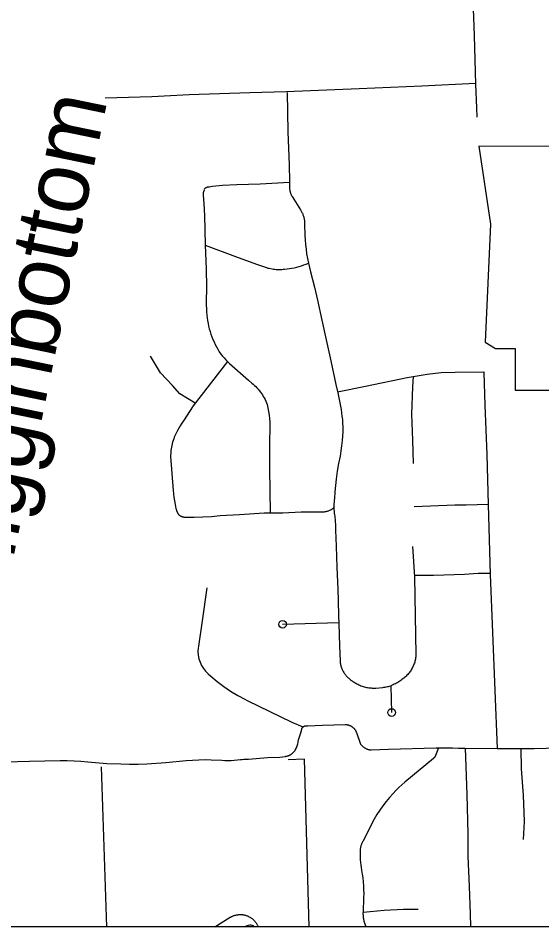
# Model space of a CAD drawing. Extents: x 309348 to 309445, y 336383 to 336484.
# Drawn here: x 309348.942 to 309349.625, y 336395.727 to 336396.912 of the extents above; entities that cross this region are included whole.
import ezdxf

# ---------------------------------------------------------------- set-up
doc = ezdxf.new("R2010")
doc.units = 0
doc.layers.add('R_Annotation', color=7, linetype='Continuous')
doc.layers.add('R_Border Notes', color=7, linetype='Continuous')

msp = doc.modelspace()

# ---------------------------------------------------------------- linework, layer by layer
at = {"layer": 'R_Annotation'}
for points in [[(309349.533, 336396.9923), (309349.5334, 336396.983), (309349.5352, 336396.9367), (309349.537, 336396.8896), (309349.5383, 336396.8422), (309349.5389, 336396.826)], [(309349.5389, 336396.8271), (309349.4687, 336396.8236), (309349.3869, 336396.82), (309349.2917, 336396.8162), (309349.2442, 336396.815), (309349.165, 336396.8123), (309349.1163, 336396.8097), (309349.0557, 336396.8079)], [(309349.5389, 336396.826), (309349.5401, 336396.7954), (309349.5405, 336396.783)], [(309349.2929, 336396.8154), (309349.2941, 336396.7641), (309349.2956, 336396.7209), (309349.2961, 336396.6994), (309349.2961, 336396.6972)], [(309349.1851, 336396.6894), (309349.1852, 336396.6896), (309349.1854, 336396.6898), (309349.1856, 336396.69), (309349.1858, 336396.6902), (309349.186, 336396.6904), (309349.1862, 336396.6906), (309349.1864, 336396.6908), (309349.1866, 336396.6909), (309349.1869, 336396.6911), (309349.1871, 336396.6913), (309349.1873, 336396.6914), (309349.1876, 336396.6915), (309349.1878, 336396.6917), (309349.1881, 336396.6918), (309349.1883, 336396.6919), (309349.1886, 336396.692), (309349.1889, 336396.6921), (309349.1891, 336396.6921), (309349.1894, 336396.6922), (309349.1897, 336396.6923), (309349.1899, 336396.6923), (309349.1902, 336396.6924), (309349.1905, 336396.6924), (309349.1908, 336396.6924), (309349.191, 336396.6924), (309349.1913, 336396.6924), (309349.1956, 336396.6931), (309349.1999, 336396.6936), (309349.2042, 336396.6941), (309349.2085, 336396.6943), (309349.2273, 336396.6954), (309349.2578, 336396.6964), (309349.2961, 336396.6984)], [(309349.2961, 336396.6972), (309349.2962, 336396.6914), (309349.2962, 336396.6906), (309349.2962, 336396.6899), (309349.2963, 336396.6891), (309349.2964, 336396.6883), (309349.2966, 336396.6875), (309349.2967, 336396.6868), (309349.2969, 336396.686), (309349.2971, 336396.6853), (309349.2973, 336396.6845), (309349.2976, 336396.6838), (309349.2979, 336396.683), (309349.2982, 336396.6823), (309349.2985, 336396.6816), (309349.2989, 336396.6809), (309349.2993, 336396.6802), (309349.2997, 336396.6796), (309349.3103, 336396.6624), (309349.3109, 336396.6616), (309349.3114, 336396.6607), (309349.3119, 336396.6597), (309349.3124, 336396.6588), (309349.3129, 336396.6578), (309349.3133, 336396.6569), (309349.3137, 336396.6559), (309349.3141, 336396.6549), (309349.3144, 336396.6539), (309349.3147, 336396.6529), (309349.315, 336396.6518), (309349.3152, 336396.6508), (309349.3154, 336396.6497), (309349.3156, 336396.6487), (309349.3157, 336396.6476), (309349.3157, 336396.6466), (309349.3158, 336396.6455), (309349.3158, 336396.6444), (309349.3158, 336396.6434), (309349.3163, 336396.629), (309349.3166, 336396.623), (309349.317, 336396.6169), (309349.3177, 336396.6108), (309349.3185, 336396.6048), (309349.3195, 336396.5988), (309349.3207, 336396.5928)], [(309349.1851, 336396.6882), (309349.1849, 336396.688), (309349.1847, 336396.6878), (309349.1846, 336396.6876), (309349.1844, 336396.6873), (309349.1843, 336396.6871), (309349.1842, 336396.6868), (309349.1841, 336396.6866), (309349.1839, 336396.6863), (309349.1838, 336396.6861), (309349.1838, 336396.6858), (309349.1837, 336396.6855), (309349.1836, 336396.6853), (309349.1835, 336396.685), (309349.1835, 336396.6847), (309349.1834, 336396.6845), (309349.1834, 336396.6842), (309349.1834, 336396.6839), (309349.1834, 336396.6836), (309349.1834, 336396.6834), (309349.1834, 336396.6831), (309349.1834, 336396.6828), (309349.1834, 336396.6825), (309349.1834, 336396.6823), (309349.1835, 336396.682), (309349.1835, 336396.6817), (309349.1836, 336396.6814), (309349.1843, 336396.67), (309349.1851, 336396.655), (309349.1859, 336396.6171), (309349.186, 336396.6161)], [(309349.186, 336396.6161), (309349.1872, 336396.5854), (309349.1878, 336396.5614), (309349.1874, 336396.542), (309349.1874, 336396.5377), (309349.1876, 336396.5334), (309349.1879, 336396.5291), (309349.1884, 336396.5249), (309349.1888, 336396.5213), (309349.1893, 336396.5177), (309349.1899, 336396.5141), (309349.1906, 336396.5106), (309349.1915, 336396.507), (309349.1925, 336396.5035), (309349.1936, 336396.5001), (309349.1948, 336396.4967), (309349.1961, 336396.4933), (309349.1976, 336396.49), (309349.1992, 336396.4867), (309349.2008, 336396.4835), (309349.2026, 336396.4803), (309349.2045, 336396.4772), (309349.2065, 336396.4742), (309349.2086, 336396.4716), (309349.2108, 336396.4691), (309349.213, 336396.4667), (309349.2153, 336396.4643)], [(309349.186, 336396.6161), (309349.2257, 336396.6013), (309349.253, 336396.5914), (309349.2662, 336396.5869), (309349.268, 336396.5864), (309349.2697, 336396.586), (309349.2715, 336396.5856), (309349.2733, 336396.5852), (309349.2751, 336396.5849), (309349.2769, 336396.5847), (309349.2788, 336396.5846), (309349.2806, 336396.5845), (309349.2824, 336396.5844), (309349.2842, 336396.5845), (309349.2861, 336396.5846), (309349.2879, 336396.5847), (309349.2897, 336396.5849), (309349.2929, 336396.5852), (309349.2961, 336396.5857), (309349.2993, 336396.5862), (309349.3024, 336396.5868), (309349.3055, 336396.5876), (309349.3086, 336396.5884), (309349.3117, 336396.5894), (309349.3148, 336396.5904), (309349.3178, 336396.5916), (309349.3207, 336396.5928)], [(309349.3207, 336396.5928), (309349.3221, 336396.5871), (309349.3236, 336396.5814), (309349.3286, 336396.5612), (309349.3326, 336396.5444), (309349.3383, 336396.5182), (309349.344, 336396.4928), (309349.3501, 336396.4651), (309349.3566, 336396.4346), (309349.359, 336396.4234)], [(309349.1732, 336396.4101), (309349.1531, 336396.4223), (309349.1434, 336396.4329), (309349.1276, 336396.4496), (309349.1146, 336396.4715)], [(309349.2153, 336396.4643), (309349.1706, 336396.4067)], [(309349.2153, 336396.4643), (309349.2179, 336396.4617), (309349.2425, 336396.4401), (309349.2471, 336396.4363), (309349.2488, 336396.4348), (309349.2505, 336396.4332), (309349.2521, 336396.4316), (309349.2537, 336396.4299), (309349.2552, 336396.4282), (309349.2567, 336396.4264), (309349.2581, 336396.4246), (309349.2595, 336396.4227), (309349.2607, 336396.4208), (309349.2619, 336396.4189), (309349.2631, 336396.4169), (309349.2642, 336396.4148), (309349.2652, 336396.4128), (309349.2661, 336396.4107), (309349.2669, 336396.4085), (309349.2679, 336396.4039)], [(309349.3586, 336396.425), (309349.3951, 336396.4324), (309349.4496, 336396.4436), (309349.4573, 336396.4448), (309349.4756, 336396.4481), (309349.4939, 336396.45), (309349.5122, 336396.4505), (309349.5497, 336396.451)], [(309349.4573, 336396.4448), (309349.4564, 336396.4312), (309349.4554, 336396.3957), (309349.4567, 336396.3617), (309349.4573, 336396.3315)], [(309349.5497, 336396.451), (309349.5497, 336396.4501)], [(309349.5497, 336396.4501), (309349.5512, 336396.4073)], [(309349.359, 336396.4234), (309349.3626, 336396.406), (309349.3634, 336396.4017), (309349.3641, 336396.3974), (309349.3646, 336396.3931), (309349.3651, 336396.3887), (309349.3653, 336396.3844), (309349.3655, 336396.3786), (309349.3655, 336396.3728), (309349.3653, 336396.3671), (309349.3649, 336396.3613), (309349.3641, 336396.3546), (309349.3632, 336396.3478), (309349.3621, 336396.3411), (309349.3602, 336396.3315), (309349.3585, 336396.3213), (309349.357, 336396.311), (309349.356, 336396.3026), (309349.3553, 336396.2942), (309349.3548, 336396.2858), (309349.3545, 336396.2834), (309349.3542, 336396.281), (309349.3541, 336396.2786), (309349.354, 336396.2762), (309349.354, 336396.2738)], [(309349.1706, 336396.4067), (309349.1576, 336396.3869), (309349.1555, 336396.3838), (309349.1536, 336396.3807), (309349.1517, 336396.3775), (309349.1499, 336396.3742), (309349.1482, 336396.3709), (309349.1466, 336396.3676), (309349.1458, 336396.3655), (309349.145, 336396.3635), (309349.1442, 336396.3614), (309349.1436, 336396.3593), (309349.143, 336396.3571), (309349.1425, 336396.355), (309349.142, 336396.3528), (309349.1416, 336396.3507), (309349.1413, 336396.3485), (309349.1411, 336396.3463), (309349.141, 336396.3407), (309349.1445, 336396.2962), (309349.1454, 336396.2875), (309349.147, 336396.2779), (309349.148, 336396.2727), (309349.1482, 336396.2718), (309349.1493, 336396.2686), (309349.1509, 336396.2655), (309349.1514, 336396.2647)], [(309349.5512, 336396.4073), (309349.5534, 336396.3433)], [(309349.2679, 336396.4039), (309349.2688, 336396.3993), (309349.2694, 336396.3946), (309349.27, 336396.3899), (309349.2703, 336396.3852), (309349.2705, 336396.3805), (309349.2706, 336396.3758), (309349.2705, 336396.3711), (309349.2702, 336396.3664), (309349.2702, 336396.3247), (309349.2709, 336396.267)], [(309349.5534, 336396.3433), (309349.5555, 336396.2778)], [(309349.5555, 336396.2778), (309349.5268, 336396.277), (309349.5117, 336396.277), (309349.4589, 336396.2748)], [(309349.5555, 336396.2778), (309349.558, 336396.1867)], [(309349.1514, 336396.2647), (309349.1517, 336396.2644), (309349.1521, 336396.2641), (309349.1524, 336396.2639), (309349.1528, 336396.2636), (309349.1531, 336396.2634), (309349.1535, 336396.2632), (309349.1539, 336396.263), (309349.1543, 336396.2628), (309349.1546, 336396.2626), (309349.155, 336396.2624), (309349.1554, 336396.2622), (309349.1558, 336396.2621), (309349.1563, 336396.262), (309349.1567, 336396.2618), (309349.1571, 336396.2617), (309349.1575, 336396.2616), (309349.1579, 336396.2616), (309349.1584, 336396.2615), (309349.1588, 336396.2615), (309349.1592, 336396.2614), (309349.1596, 336396.2614), (309349.1601, 336396.2614), (309349.1605, 336396.2614), (309349.1719, 336396.2614), (309349.1832, 336396.2617), (309349.1945, 336396.2624), (309349.2058, 336396.2635)], [(309349.2058, 336396.2635), (309349.2309, 336396.265), (309349.263, 336396.267), (309349.2709, 336396.267)], [(309349.2709, 336396.267), (309349.2873, 336396.2671), (309349.3114, 336396.2681), (309349.3378, 336396.2683), (309349.3386, 336396.2683), (309349.3394, 336396.2683), (309349.3402, 336396.2683), (309349.341, 336396.2684), (309349.3418, 336396.2685), (309349.3426, 336396.2686), (309349.3434, 336396.2687), (309349.3441, 336396.2689), (309349.3449, 336396.2691), (309349.3457, 336396.2693), (309349.3464, 336396.2695), (309349.3472, 336396.2698), (309349.3479, 336396.2701), (309349.3487, 336396.2704), (309349.3494, 336396.2708), (309349.3501, 336396.2711), (309349.3508, 336396.2715), (309349.3515, 336396.2719), (309349.3521, 336396.2724), (309349.3528, 336396.2728), (309349.3534, 336396.2733), (309349.354, 336396.2738)], [(309349.354, 336396.2738), (309349.3541, 336396.2715), (309349.3542, 336396.2691), (309349.3545, 336396.2667), (309349.3548, 336396.2644), (309349.3551, 336396.2627), (309349.3556, 336396.2566), (309349.3561, 336396.2505), (309349.3563, 336396.2444), (309349.3569, 336396.2237), (309349.3579, 336396.1956), (309349.359, 336396.1676), (309349.3596, 336396.152), (309349.36, 336396.1325), (309349.3603, 336396.1227)], [(309349.4565, 336396.223), (309349.459, 336396.1837)], [(309349.459, 336396.1837), (309349.4611, 336396.082), (309349.461, 336396.0806), (309349.4609, 336396.0791), (309349.4607, 336396.0777), (309349.4605, 336396.0763), (309349.4602, 336396.0749), (309349.4598, 336396.0735), (309349.4595, 336396.0722), (309349.459, 336396.0708), (309349.4585, 336396.0694), (309349.458, 336396.0681), (309349.4574, 336396.0668), (309349.4568, 336396.0655), (309349.4562, 336396.0642), (309349.4555, 336396.063), (309349.4547, 336396.0618), (309349.4539, 336396.0606), (309349.4531, 336396.0594), (309349.4522, 336396.0583), (309349.4513, 336396.0572), (309349.4504, 336396.0561), (309349.4494, 336396.0551), (309349.4484, 336396.0541), (309349.4473, 336396.0531), (309349.4463, 336396.0522), (309349.4451, 336396.0513), (309349.444, 336396.0504), (309349.4427, 336396.0494), (309349.4414, 336396.0483), (309349.4401, 336396.0474), (309349.4387, 336396.0465), (309349.4373, 336396.0456), (309349.4359, 336396.0448), (309349.4344, 336396.044), (309349.4329, 336396.0433), (309349.4314, 336396.0427), (309349.4299, 336396.0421), (309349.4283, 336396.0415)], [(309349.4589, 336396.1856), (309349.4839, 336396.1856), (309349.5244, 336396.1868), (309349.5425, 336396.1882), (309349.558, 336396.1882)], [(309349.558, 336396.1867), (309349.567, 336395.9596)], [(309349.1884, 336396.169), (309349.1822, 336396.1259), (309349.1772, 336396.093), (309349.1769, 336396.0906), (309349.1767, 336396.0859), (309349.1771, 336396.0813), (309349.178, 336396.0767), (309349.1794, 336396.0723), (309349.1813, 336396.068), (309349.1837, 336396.064), (309349.1866, 336396.0604), (309349.1898, 336396.0571), (309349.1936, 336396.0537), (309349.2018, 336396.0469), (309349.2104, 336396.0404), (309349.2193, 336396.0344), (309349.2285, 336396.0288), (309349.238, 336396.0237), (309349.2408, 336396.0223), (309349.2991, 336395.9937), (309349.3137, 336395.9876)], [(309349.2871, 336396.1216), (309349.3603, 336396.1238)], [(309349.3603, 336396.1227), (309349.3614, 336396.0934), (309349.3621, 336396.0736), (309349.3622, 336396.0724), (309349.3624, 336396.0713), (309349.3626, 336396.0702), (309349.3628, 336396.0691), (309349.363, 336396.068), (309349.3633, 336396.067), (309349.3636, 336396.0659), (309349.364, 336396.0648), (309349.3644, 336396.0638), (309349.3648, 336396.0628), (309349.3653, 336396.0618), (309349.3658, 336396.0608), (309349.3663, 336396.0598), (309349.3669, 336396.0588), (309349.3675, 336396.0579), (309349.3681, 336396.057), (309349.3688, 336396.0561), (309349.3695, 336396.0552), (309349.3702, 336396.0543), (309349.3709, 336396.0535), (309349.3717, 336396.0527), (309349.3725, 336396.0519), (309349.3734, 336396.0512), (309349.3742, 336396.0505), (309349.3751, 336396.0497), (309349.3759, 336396.049), (309349.3768, 336396.0483), (309349.3777, 336396.0477), (309349.3787, 336396.047), (309349.3796, 336396.0464), (309349.3806, 336396.0459), (309349.3816, 336396.0453), (309349.3826, 336396.0448), (309349.3839, 336396.0441), (309349.3852, 336396.0433), (309349.3866, 336396.0427), (309349.3879, 336396.042), (309349.3893, 336396.0415), (309349.3908, 336396.0409), (309349.3922, 336396.0405), (309349.3936, 336396.04), (309349.3951, 336396.0396), (309349.3966, 336396.0393), (309349.3981, 336396.039), (309349.3996, 336396.0388), (309349.4011, 336396.0386), (309349.4026, 336396.0385), (309349.4041, 336396.0384), (309349.4056, 336396.0383), (309349.4071, 336396.0384), (309349.4086, 336396.0384), (309349.4179, 336396.0393), (309349.4194, 336396.0394), (309349.4209, 336396.0397), (309349.4224, 336396.0399), (309349.4239, 336396.0403), (309349.4254, 336396.0406), (309349.4268, 336396.041), (309349.4283, 336396.0415)], [(309349.4283, 336396.0415), (309349.4293, 336396.0065)], [(309349.3137, 336395.9876), (309349.3139, 336395.9877), (309349.314, 336395.9878), (309349.3142, 336395.9879), (309349.3143, 336395.9881), (309349.3145, 336395.9882), (309349.3146, 336395.9883), (309349.3148, 336395.9884), (309349.315, 336395.9885), (309349.3151, 336395.9885), (309349.3153, 336395.9886), (309349.3155, 336395.9887), (309349.3157, 336395.9888), (309349.3158, 336395.9888), (309349.316, 336395.9889), (309349.3162, 336395.9889), (309349.3164, 336395.989), (309349.3166, 336395.989), (309349.3168, 336395.989), (309349.3202, 336395.9892), (309349.3393, 336395.9898), (309349.3686, 336395.9909), (309349.3691, 336395.9908), (309349.3697, 336395.9908), (309349.3702, 336395.9908), (309349.3708, 336395.9907), (309349.3713, 336395.9906), (309349.3719, 336395.9905), (309349.3724, 336395.9904), (309349.373, 336395.9902), (309349.3735, 336395.9901), (309349.374, 336395.9899), (309349.3745, 336395.9897), (309349.3751, 336395.9894), (309349.3756, 336395.9892), (309349.3761, 336395.989), (309349.3765, 336395.9887), (309349.377, 336395.9884), (309349.3775, 336395.9881), (309349.3779, 336395.9878), (309349.3784, 336395.9874), (309349.3788, 336395.9871), (309349.3792, 336395.9867), (309349.3796, 336395.9863), (309349.38, 336395.9859), (309349.3804, 336395.9855), (309349.3808, 336395.9851), (309349.3811, 336395.9847), (309349.3815, 336395.9842), (309349.3818, 336395.9838), (309349.3821, 336395.9833), (309349.3824, 336395.9828), (309349.3826, 336395.9823), (309349.3829, 336395.9818), (309349.3831, 336395.9813), (309349.3833, 336395.9808), (309349.3835, 336395.9803), (309349.3887, 336395.9654), (309349.3891, 336395.9649), (309349.3895, 336395.9644), (309349.3899, 336395.9639), (309349.3904, 336395.9634), (309349.3909, 336395.963), (309349.3913, 336395.9625), (309349.3918, 336395.9621), (309349.3924, 336395.9617), (309349.3929, 336395.9613), (309349.3934, 336395.9609), (309349.394, 336395.9606), (309349.3945, 336395.9602), (309349.3951, 336395.9599), (309349.3957, 336395.9596), (309349.3963, 336395.9593), (309349.3969, 336395.9591), (309349.3975, 336395.9588), (309349.3981, 336395.9586), (309349.3988, 336395.9584), (309349.3994, 336395.9583), (309349.4001, 336395.9581), (309349.4007, 336395.958), (309349.4014, 336395.9579), (309349.402, 336395.9578), (309349.4027, 336395.9577), (309349.4252, 336395.9586), (309349.4873, 336395.9605), (309349.4905, 336395.9605)], [(309349.3022, 336395.9557), (309349.3026, 336395.9561), (309349.303, 336395.9566), (309349.3033, 336395.9571), (309349.3036, 336395.9576), (309349.3039, 336395.9581), (309349.3042, 336395.9587), (309349.3045, 336395.9592), (309349.3051, 336395.9605), (309349.3056, 336395.9618), (309349.3061, 336395.9631), (309349.3066, 336395.9645), (309349.307, 336395.9658), (309349.3073, 336395.9672), (309349.3076, 336395.9685), (309349.308, 336395.9707), (309349.3089, 336395.9736), (309349.3107, 336395.9801), (309349.3121, 336395.9849), (309349.3121, 336395.9851), (309349.3122, 336395.9853), (309349.3123, 336395.9855), (309349.3123, 336395.9857), (309349.3124, 336395.9858), (309349.3125, 336395.986), (309349.3126, 336395.9862), (309349.3127, 336395.9864), (309349.3128, 336395.9865), (309349.3129, 336395.9867), (309349.313, 336395.9869), (309349.3132, 336395.987), (309349.3133, 336395.9872), (309349.3134, 336395.9873), (309349.3136, 336395.9874), (309349.3137, 336395.9876)], [(309348.91, 336395.9419), (309348.9567, 336395.9429), (309348.9969, 336395.9438), (309349.006, 336395.9439), (309349.015, 336395.9436), (309349.024, 336395.943), (309349.033, 336395.942), (309349.0576, 336395.9401), (309349.0762, 336395.9394), (309349.0874, 336395.9391), (309349.0986, 336395.9392), (309349.1098, 336395.9397), (309349.1346, 336395.9412), (309349.1613, 336395.9438), (309349.1695, 336395.9445), (309349.1777, 336395.9448), (309349.1859, 336395.945), (309349.194, 336395.9448), (309349.2077, 336395.9441), (309349.2118, 336395.9439), (309349.2159, 336395.9439), (309349.22, 336395.944), (309349.2241, 336395.9442), (309349.2282, 336395.9446), (309349.2323, 336395.9451), (309349.2344, 336395.9453), (309349.2365, 336395.9455), (309349.2386, 336395.9456), (309349.2407, 336395.9457), (309349.2428, 336395.9457), (309349.2675, 336395.9478), (309349.2833, 336395.9484), (309349.2903, 336395.9492), (309349.2909, 336395.9493), (309349.2915, 336395.9494), (309349.2921, 336395.9495), (309349.2927, 336395.9496), (309349.2933, 336395.9498), (309349.2939, 336395.9499), (309349.2944, 336395.9501), (309349.295, 336395.9503), (309349.2956, 336395.9506), (309349.2961, 336395.9508), (309349.2966, 336395.9511), (309349.2972, 336395.9514), (309349.2977, 336395.9517), (309349.2982, 336395.952), (309349.2987, 336395.9524), (309349.2992, 336395.9527), (309349.2997, 336395.9531), (309349.3001, 336395.9535), (309349.3006, 336395.9539), (309349.301, 336395.9543), (309349.3014, 336395.9547), (309349.3018, 336395.9552), (309349.3022, 336395.9557)], [(309349.4905, 336395.9605), (309349.4867, 336395.9505), (309349.4865, 336395.9501), (309349.4863, 336395.9497), (309349.4861, 336395.9493), (309349.4859, 336395.9489), (309349.4856, 336395.9485), (309349.4854, 336395.9482), (309349.4851, 336395.9478), (309349.4848, 336395.9475), (309349.4845, 336395.9472), (309349.4842, 336395.9468), (309349.4839, 336395.9465), (309349.4464, 336395.9155), (309349.4425, 336395.912), (309349.4387, 336395.9085), (309349.435, 336395.9048), (309349.4314, 336395.901), (309349.4268, 336395.8957), (309349.4224, 336395.8903), (309349.4181, 336395.8848), (309349.414, 336395.8791), (309349.4101, 336395.8733), (309349.4064, 336395.8673), (309349.3919, 336395.8382), (309349.3915, 336395.8376), (309349.3911, 336395.837), (309349.3908, 336395.8363), (309349.3905, 336395.8357), (309349.3902, 336395.835), (309349.3899, 336395.8343), (309349.3896, 336395.8336), (309349.3894, 336395.8329), (309349.3892, 336395.8322), (309349.389, 336395.8315), (309349.3889, 336395.8308), (309349.3887, 336395.8301), (309349.3886, 336395.8294), (309349.3885, 336395.8286), (309349.3885, 336395.8279), (309349.3883, 336395.8245), (309349.3882, 336395.8211), (309349.3882, 336395.8177), (309349.3884, 336395.8143), (309349.3886, 336395.8109), (309349.389, 336395.8075), (309349.3895, 336395.8041), (309349.39, 336395.8008), (309349.3909, 336395.7957), (309349.3916, 336395.7907), (309349.3922, 336395.7856), (309349.3926, 336395.7805), (309349.3928, 336395.7753), (309349.3929, 336395.7702), (309349.3928, 336395.7651), (309349.3921, 336395.7458)], [(309349.4905, 336395.9605), (309349.5087, 336395.9604), (309349.5165, 336395.9601), (309349.5253, 336395.96)], [(309349.5253, 336395.96), (309349.5277, 336395.8996), (309349.5289, 336395.8483), (309349.529, 336395.8191), (309349.5306, 336395.7795), (309349.532, 336395.7439), (309349.5323, 336395.7269)], [(309349.5253, 336395.96), (309349.567, 336395.9596)], [(309349.567, 336395.9596), (309349.5978, 336395.9596)], [(309349.5978, 336395.9596), (309349.6152, 336395.9596), (309349.6786, 336395.9612), (309349.7392, 336395.9643)], [(309349.5978, 336395.9596), (309349.5985, 336395.9331), (309349.6008, 336395.8988), (309349.6024, 336395.8641), (309349.6012, 336395.8407)], [(309349.3216, 336395.7269), (309349.3159, 336395.9458), (309349.2943, 336395.9449)], [(309349.0503, 336395.9355), (309349.0574, 336395.7269)], [(309349.1985, 336395.7269), (309349.2188, 336395.7393), (309349.2196, 336395.7397), (309349.2203, 336395.7402), (309349.2211, 336395.7405), (309349.2219, 336395.7409), (309349.2227, 336395.7412), (309349.2235, 336395.7415), (309349.2243, 336395.7418), (309349.2251, 336395.7421), (309349.226, 336395.7423), (309349.2268, 336395.7425), (309349.2277, 336395.7426), (309349.2285, 336395.7427), (309349.2294, 336395.7428), (309349.2303, 336395.7429), (309349.2311, 336395.7429), (309349.232, 336395.743), (309349.2329, 336395.7429), (309349.2337, 336395.7429), (309349.2346, 336395.7428), (309349.2354, 336395.7427), (309349.2363, 336395.7425), (309349.2371, 336395.7424), (309349.238, 336395.7422), (309349.2388, 336395.7419), (309349.2396, 336395.7417), (309349.2405, 336395.7414), (309349.2413, 336395.7411), (309349.2421, 336395.7407), (309349.2428, 336395.7404), (309349.2436, 336395.74), (309349.2444, 336395.7396), (309349.2451, 336395.7391), (309349.2458, 336395.7386), (309349.2465, 336395.7381), (309349.2472, 336395.7376), (309349.2479, 336395.7371), (309349.2486, 336395.7365), (309349.2492, 336395.7359), (309349.2498, 336395.7353), (309349.2504, 336395.7346), (309349.251, 336395.734), (309349.2515, 336395.7333), (309349.252, 336395.7326), (309349.2525, 336395.7319), (309349.253, 336395.7312), (309349.2534, 336395.7304), (309349.2538, 336395.7297), (309349.2542, 336395.7289), (309349.2546, 336395.7281), (309349.2549, 336395.7273), (309349.2551, 336395.7269)], [(309349.3921, 336395.7458), (309349.392, 336395.7448), (309349.392, 336395.7436), (309349.3921, 336395.7424), (309349.3921, 336395.7413), (309349.3922, 336395.7401), (309349.3924, 336395.7389), (309349.3926, 336395.7377), (309349.3928, 336395.7366), (309349.393, 336395.7354), (309349.3933, 336395.7342), (309349.3937, 336395.7331), (309349.394, 336395.732), (309349.3945, 336395.7309), (309349.3956, 336395.7269)], [(309349.3921, 336395.7458), (309349.4198, 336395.7485), (309349.4281, 336395.7492), (309349.4365, 336395.7497), (309349.4448, 336395.75), (309349.4532, 336395.75), (309349.4638, 336395.7499)], [(309349.2503, 336395.7269), (309349.2499, 336395.7274), (309349.249, 336395.728), (309349.2473, 336395.7288), (309349.2461, 336395.7291), (309349.2444, 336395.7291), (309349.242, 336395.7285), (309349.2383, 336395.7271), (309349.238, 336395.7269)]]:
    msp.add_lwpolyline(points, dxfattribs=at)
msp.add_lwpolyline([(309349.543, 336396.7453), (309349.5582, 336396.6437), (309349.5515, 336396.4897), (309349.565, 336396.4813), (309349.5904, 336396.4813), (309349.5904, 336396.4271), (309349.8036, 336396.4271), (309349.8138, 336396.4491), (309349.8104, 336396.4846), (309349.8155, 336396.5253), (309349.8341, 336396.5574), (309349.8459, 336396.5811), (309349.8628, 336396.6065), (309349.873, 336396.6336), (309349.8815, 336396.6556), (309349.8967, 336396.6742), (309349.9001, 336396.686), (309349.8933, 336396.6945), (309349.8408, 336396.6945), (309349.8527, 336396.7182), (309349.8544, 336396.7334), (309349.8474, 336396.7451)], close=True, dxfattribs=at)
for centre in [(309349.2871, 336396.1216), (309349.4293, 336396.0065)]:
    msp.add_circle(centre, 0.005, dxfattribs=at)
at = {"layer": 'R_Border Notes'}
msp.add_line((309356.3641, 336395.7269), (309347.6607, 336395.7269), dxfattribs=at)

# ---------------------------------------------------------------- texts
at = {"layer": 'R_Annotation'}
msp.add_text('Higginbottom', height=0.084508, rotation=78.3762, dxfattribs=at).set_placement((309348.9245, 336396.153))

doc.saveas('drawing.dxf')
